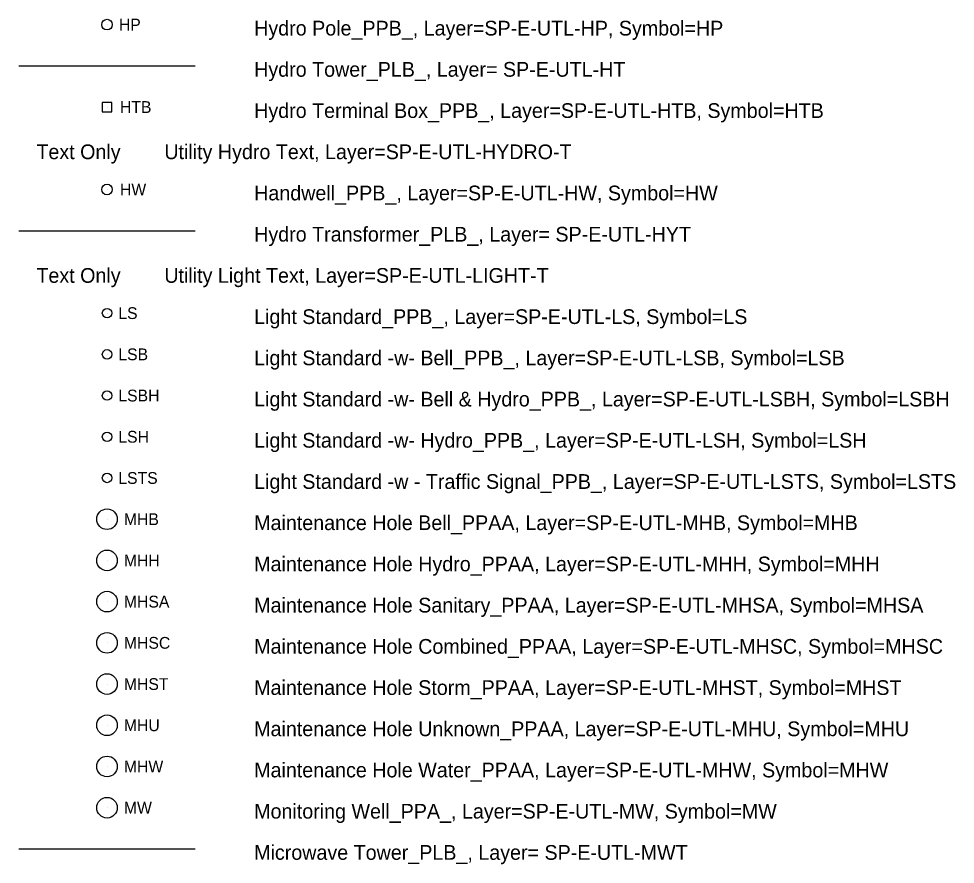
# Model space of a CAD drawing. Extents: x 500528 to 502626, y 4210261 to 4212624.
# Drawn here: x 500886.5 to 501045.7, y 4210853 to 4210996.6 of the extents above; entities that cross this region are included whole.
import ezdxf

# ---------------------------------------------------------------- set-up
doc = ezdxf.new("R2010")
doc.units = 0
for name, color, linetype in [('SP-E-UTL-BELL-T', 7, 'Continuous'), ('SP-E-UTL-COMB-T', 7, 'Continuous'), ('SP-E-UTL-HP', 7, 'Continuous'), ('SP-E-UTL-HT', 7, 'Continuous'), ('SP-E-UTL-HTB', 7, 'Continuous'), ('SP-E-UTL-HW', 7, 'Continuous'), ('SP-E-UTL-HYDRO-T', 7, 'Continuous'), ('SP-E-UTL-HYT', 7, 'Continuous'), ('SP-E-UTL-LIGHT-T', 7, 'Continuous'), ('SP-E-UTL-LS', 7, 'Continuous'), ('SP-E-UTL-LSB', 7, 'Continuous'), ('SP-E-UTL-LSBH', 7, 'Continuous'), ('SP-E-UTL-LSH', 7, 'Continuous'), ('SP-E-UTL-LSTS', 7, 'Continuous'), ('SP-E-UTL-MHB', 7, 'Continuous'), ('SP-E-UTL-MHH', 7, 'Continuous'), ('SP-E-UTL-MHSA', 7, 'Continuous'), ('SP-E-UTL-MHSC', 7, 'Continuous'), ('SP-E-UTL-MHST', 7, 'Continuous'), ('SP-E-UTL-MHU', 7, 'Continuous'), ('SP-E-UTL-MHW', 7, 'Continuous'), ('SP-E-UTL-MW', 7, 'Continuous'), ('SP-E-UTL-MWT', 7, 'Continuous'), ('SP-E-UTL-SAN-ST-COMB-T', 7, 'Continuous'), ('SP-E-UTL-SAN-T', 7, 'Continuous'), ('SP-E-UTL-STORM-T', 7, 'Continuous'), ('SP-E-UTL-T', 7, 'Continuous'), ('SP-E-UTL-WATER-T', 7, 'Continuous')]:
    doc.layers.add(name, color=color, linetype=linetype)

# ---------------------------------------------------------------- blocks, each defined once
blk = doc.blocks.new('HP')
at = {"layer": 'SP-E-UTL-HP'}
blk.add_lwpolyline([(0, 0), (0, 0)], dxfattribs=at)
blk.add_circle((0, 0), 0.09, dxfattribs=at)
at = {"layer": 'SP-E-UTL-HYDRO-T'}
blk.add_text('HP', height=0.2, dxfattribs=at).set_placement((0.202, -0.1))
blk = doc.blocks.new('HTB')
at = {"layer": 'SP-E-UTL-HTB'}
for points in [[(-0.08, 0.08), (-0.08, -0.08), (0.08, -0.08), (0.08, 0.08), (-0.08, 0.08)], [(0, 0), (0, 0)]]:
    blk.add_lwpolyline(points, dxfattribs=at)
at = {"layer": 'SP-E-UTL-HYDRO-T'}
blk.add_text('HTB', height=0.2, dxfattribs=at).set_placement((0.22, -0.1))
blk = doc.blocks.new('HW')
at = {"layer": 'SP-E-UTL-HW'}
blk.add_lwpolyline([(0, 0), (0, 0)], dxfattribs=at)
blk.add_circle((0, 0), 0.09, dxfattribs=at)
at = {"layer": 'SP-E-UTL-T'}
blk.add_text('HW', height=0.2, dxfattribs=at).set_placement((0.22, -0.1))
blk = doc.blocks.new('LS')
at = {"layer": 'SP-E-UTL-LS'}
blk.add_lwpolyline([(0, 0), (0, 0)], dxfattribs=at)
blk.add_circle((0, 0), 0.08, dxfattribs=at)
at = {"layer": 'SP-E-UTL-LIGHT-T'}
blk.add_text('LS', height=0.2, dxfattribs=at).set_placement((0.192, -0.1))
blk = doc.blocks.new('LSB')
at = {"layer": 'SP-E-UTL-LSB'}
blk.add_lwpolyline([(0, 0), (0, 0)], dxfattribs=at)
blk.add_circle((0, 0), 0.08, dxfattribs=at)
at = {"layer": 'SP-E-UTL-COMB-T'}
blk.add_text('LSB', height=0.2, dxfattribs=at).set_placement((0.192, -0.1))
blk = doc.blocks.new('LSBH')
at = {"layer": 'SP-E-UTL-LSBH'}
blk.add_lwpolyline([(0, 0), (0, 0)], dxfattribs=at)
blk.add_circle((0, 0), 0.08, dxfattribs=at)
at = {"layer": 'SP-E-UTL-COMB-T'}
blk.add_text('LSBH', height=0.2, dxfattribs=at).set_placement((0.192, -0.1))
blk = doc.blocks.new('LSH')
at = {"layer": 'SP-E-UTL-LSH'}
blk.add_lwpolyline([(0, 0), (0, 0)], dxfattribs=at)
blk.add_circle((0, 0), 0.08, dxfattribs=at)
at = {"layer": 'SP-E-UTL-COMB-T'}
blk.add_text('LSH', height=0.2, dxfattribs=at).set_placement((0.192, -0.1))
blk = doc.blocks.new('LSTS')
at = {"layer": 'SP-E-UTL-LSTS'}
blk.add_lwpolyline([(0, 0), (0, 0)], dxfattribs=at)
blk.add_circle((0, 0), 0.08, dxfattribs=at)
at = {"layer": 'SP-E-UTL-COMB-T'}
blk.add_text('LSTS', height=0.2, dxfattribs=at).set_placement((0.192, -0.1))
blk = doc.blocks.new('MHB')
at = {"layer": 'SP-E-UTL-MHB'}
blk.add_lwpolyline([(0, 0), (0, 0)], dxfattribs=at)
blk.add_circle((0, 0), 0.175, dxfattribs=at)
at = {"layer": 'SP-E-UTL-BELL-T'}
blk.add_text('MHB', height=0.2, dxfattribs=at).set_placement((0.287, -0.1))
blk = doc.blocks.new('MHH')
at = {"layer": 'SP-E-UTL-MHH'}
blk.add_lwpolyline([(0, 0), (0, 0)], dxfattribs=at)
blk.add_circle((0, 0), 0.175, dxfattribs=at)
at = {"layer": 'SP-E-UTL-HYDRO-T'}
blk.add_text('MHH', height=0.2, dxfattribs=at).set_placement((0.287, -0.1))
blk = doc.blocks.new('MHSA')
at = {"layer": 'SP-E-UTL-MHSA'}
blk.add_lwpolyline([(0, 0), (0, 0)], dxfattribs=at)
blk.add_circle((0, 0), 0.175, dxfattribs=at)
at = {"layer": 'SP-E-UTL-SAN-T'}
blk.add_text('MHSA', height=0.2, dxfattribs=at).set_placement((0.287, -0.1))
blk = doc.blocks.new('MHSC')
at = {"layer": 'SP-E-UTL-MHSC'}
blk.add_lwpolyline([(0, 0), (0, 0)], dxfattribs=at)
blk.add_circle((0, 0), 0.175, dxfattribs=at)
at = {"layer": 'SP-E-UTL-SAN-ST-COMB-T'}
blk.add_text('MHSC', height=0.2, dxfattribs=at).set_placement((0.287, -0.1))
blk = doc.blocks.new('MHST')
at = {"layer": 'SP-E-UTL-MHST'}
blk.add_lwpolyline([(0, 0), (0, 0)], dxfattribs=at)
blk.add_circle((0, 0), 0.175, dxfattribs=at)
at = {"layer": 'SP-E-UTL-STORM-T'}
blk.add_text('MHST', height=0.2, dxfattribs=at).set_placement((0.287, -0.1))
blk = doc.blocks.new('MHU')
at = {"layer": 'SP-E-UTL-MHU'}
blk.add_lwpolyline([(0, 0), (0, 0)], dxfattribs=at)
blk.add_circle((0, 0), 0.175, dxfattribs=at)
at = {"layer": 'SP-E-UTL-T'}
blk.add_text('MHU', height=0.2, dxfattribs=at).set_placement((0.287, -0.1))
blk = doc.blocks.new('MHW')
at = {"layer": 'SP-E-UTL-MHW'}
blk.add_lwpolyline([(0, 0), (0, 0)], dxfattribs=at)
blk.add_circle((0, 0), 0.175, dxfattribs=at)
at = {"layer": 'SP-E-UTL-WATER-T'}
blk.add_text('MHW', height=0.2, dxfattribs=at).set_placement((0.287, -0.1))
blk = doc.blocks.new('MW')
at = {"layer": 'SP-E-UTL-MW'}
blk.add_lwpolyline([(0, 0), (0, 0)], dxfattribs=at)
blk.add_circle((0, 0), 0.175, dxfattribs=at)
at = {"layer": 'SP-E-UTL-T'}
blk.add_text('MW', height=0.2, dxfattribs=at).set_placement((0.287, -0.1))

msp = doc.modelspace()

# ---------------------------------------------------------------- linework, layer by layer
at = {"layer": 'SP-E-UTL-HT'}
msp.add_line((500886.55, 4210988.59), (500916.55, 4210988.59), dxfattribs=at)
at = {"layer": 'SP-E-UTL-HYT'}
msp.add_line((500886.55, 4210960.59), (500916.55, 4210960.59), dxfattribs=at)
at = {"layer": 'SP-E-UTL-MWT'}
msp.add_line((500886.55, 4210855.59), (500916.55, 4210855.59), dxfattribs=at)

# ---------------------------------------------------------------- block references
at = {"layer": 'SP-E-UTL-HP', "xscale": 10, "yscale": 10}
msp.add_blockref('HP', (500901.55, 4210995.59), dxfattribs=at)
at = {"layer": 'SP-E-UTL-HTB', "xscale": 10, "yscale": 10}
msp.add_blockref('HTB', (500901.55, 4210981.59), dxfattribs=at)
at = {"layer": 'SP-E-UTL-HW', "xscale": 10, "yscale": 10}
msp.add_blockref('HW', (500901.55, 4210967.59), dxfattribs=at)
at = {"layer": 'SP-E-UTL-LS', "xscale": 10, "yscale": 10}
msp.add_blockref('LS', (500901.55, 4210946.59), dxfattribs=at)
at = {"layer": 'SP-E-UTL-LSB', "xscale": 10, "yscale": 10}
msp.add_blockref('LSB', (500901.55, 4210939.59), dxfattribs=at)
at = {"layer": 'SP-E-UTL-LSBH', "xscale": 10, "yscale": 10}
msp.add_blockref('LSBH', (500901.55, 4210932.59), dxfattribs=at)
at = {"layer": 'SP-E-UTL-LSH', "xscale": 10, "yscale": 10}
msp.add_blockref('LSH', (500901.55, 4210925.59), dxfattribs=at)
at = {"layer": 'SP-E-UTL-LSTS', "xscale": 10, "yscale": 10}
msp.add_blockref('LSTS', (500901.55, 4210918.59), dxfattribs=at)
at = {"layer": 'SP-E-UTL-MHB', "xscale": 10, "yscale": 10}
msp.add_blockref('MHB', (500901.55, 4210911.59), dxfattribs=at)
at = {"layer": 'SP-E-UTL-MHH', "xscale": 10, "yscale": 10}
msp.add_blockref('MHH', (500901.55, 4210904.59), dxfattribs=at)
at = {"layer": 'SP-E-UTL-MHSA', "xscale": 10, "yscale": 10}
msp.add_blockref('MHSA', (500901.55, 4210897.59), dxfattribs=at)
at = {"layer": 'SP-E-UTL-MHSC', "xscale": 10, "yscale": 10}
msp.add_blockref('MHSC', (500901.55, 4210890.59), dxfattribs=at)
at = {"layer": 'SP-E-UTL-MHST', "xscale": 10, "yscale": 10}
msp.add_blockref('MHST', (500901.55, 4210883.59), dxfattribs=at)
at = {"layer": 'SP-E-UTL-MHU', "xscale": 10, "yscale": 10}
msp.add_blockref('MHU', (500901.55, 4210876.59), dxfattribs=at)
at = {"layer": 'SP-E-UTL-MHW', "xscale": 10, "yscale": 10}
msp.add_blockref('MHW', (500901.55, 4210869.59), dxfattribs=at)
at = {"layer": 'SP-E-UTL-MW', "xscale": 10, "yscale": 10}
msp.add_blockref('MW', (500901.55, 4210862.59), dxfattribs=at)

# ---------------------------------------------------------------- texts
at = {"layer": 'SP-E-UTL-HP'}
msp.add_text('Hydro Pole_PPB_, Layer=SP-E-UTL-HP, Symbol=HP ', height=2.5, dxfattribs=at).set_placement((500926.55, 4210993.74))
at = {"layer": 'SP-E-UTL-HT'}
msp.add_text('Hydro Tower_PLB_, Layer= SP-E-UTL-HT ', height=2.5, dxfattribs=at).set_placement((500926.55, 4210986.74))
at = {"layer": 'SP-E-UTL-HTB'}
msp.add_text('Hydro Terminal Box_PPB_, Layer=SP-E-UTL-HTB, Symbol=HTB ', height=2.5, dxfattribs=at).set_placement((500926.55, 4210979.74))
at = {"layer": 'SP-E-UTL-HW'}
msp.add_text('Handwell_PPB_, Layer=SP-E-UTL-HW, Symbol=HW ', height=2.5, dxfattribs=at).set_placement((500926.55, 4210965.74))
at = {"layer": 'SP-E-UTL-HYDRO-T'}
msp.add_text('Text Only        Utility Hydro Text, Layer=SP-E-UTL-HYDRO-T', height=2.5, dxfattribs=at).set_placement((500889.55, 4210972.74))
at = {"layer": 'SP-E-UTL-HYT'}
msp.add_text('Hydro Transformer_PLB_, Layer= SP-E-UTL-HYT ', height=2.5, dxfattribs=at).set_placement((500926.55, 4210958.74))
at = {"layer": 'SP-E-UTL-LIGHT-T'}
msp.add_text('Text Only        Utility Light Text, Layer=SP-E-UTL-LIGHT-T', height=2.5, dxfattribs=at).set_placement((500889.55, 4210951.74))
at = {"layer": 'SP-E-UTL-LS'}
msp.add_text('Light Standard_PPB_, Layer=SP-E-UTL-LS, Symbol=LS ', height=2.5, dxfattribs=at).set_placement((500926.55, 4210944.74))
at = {"layer": 'SP-E-UTL-LSB'}
msp.add_text('Light Standard -w- Bell_PPB_, Layer=SP-E-UTL-LSB, Symbol=LSB ', height=2.5, dxfattribs=at).set_placement((500926.55, 4210937.74))
at = {"layer": 'SP-E-UTL-LSBH'}
msp.add_text('Light Standard -w- Bell & Hydro_PPB_, Layer=SP-E-UTL-LSBH, Symbol=LSBH ', height=2.5, dxfattribs=at).set_placement((500926.55, 4210930.74))
at = {"layer": 'SP-E-UTL-LSH'}
msp.add_text('Light Standard -w- Hydro_PPB_, Layer=SP-E-UTL-LSH, Symbol=LSH ', height=2.5, dxfattribs=at).set_placement((500926.55, 4210923.74))
at = {"layer": 'SP-E-UTL-LSTS'}
msp.add_text('Light Standard -w - Traffic Signal_PPB_, Layer=SP-E-UTL-LSTS, Symbol=LSTS ', height=2.5, dxfattribs=at).set_placement((500926.55, 4210916.74))
at = {"layer": 'SP-E-UTL-MHB'}
msp.add_text('Maintenance Hole Bell_PPAA, Layer=SP-E-UTL-MHB, Symbol=MHB ', height=2.5, dxfattribs=at).set_placement((500926.55, 4210909.74))
at = {"layer": 'SP-E-UTL-MHH'}
msp.add_text('Maintenance Hole Hydro_PPAA, Layer=SP-E-UTL-MHH, Symbol=MHH ', height=2.5, dxfattribs=at).set_placement((500926.55, 4210902.74))
at = {"layer": 'SP-E-UTL-MHSA'}
msp.add_text('Maintenance Hole Sanitary_PPAA, Layer=SP-E-UTL-MHSA, Symbol=MHSA ', height=2.5, dxfattribs=at).set_placement((500926.55, 4210895.74))
at = {"layer": 'SP-E-UTL-MHSC'}
msp.add_text('Maintenance Hole Combined_PPAA, Layer=SP-E-UTL-MHSC, Symbol=MHSC ', height=2.5, dxfattribs=at).set_placement((500926.55, 4210888.74))
at = {"layer": 'SP-E-UTL-MHST'}
msp.add_text('Maintenance Hole Storm_PPAA, Layer=SP-E-UTL-MHST, Symbol=MHST ', height=2.5, dxfattribs=at).set_placement((500926.55, 4210881.74))
at = {"layer": 'SP-E-UTL-MHU'}
msp.add_text('Maintenance Hole Unknown_PPAA, Layer=SP-E-UTL-MHU, Symbol=MHU ', height=2.5, dxfattribs=at).set_placement((500926.55, 4210874.74))
at = {"layer": 'SP-E-UTL-MHW'}
msp.add_text('Maintenance Hole Water_PPAA, Layer=SP-E-UTL-MHW, Symbol=MHW ', height=2.5, dxfattribs=at).set_placement((500926.55, 4210867.74))
at = {"layer": 'SP-E-UTL-MW'}
msp.add_text('Monitoring Well_PPA_, Layer=SP-E-UTL-MW, Symbol=MW ', height=2.5, dxfattribs=at).set_placement((500926.55, 4210860.74))
at = {"layer": 'SP-E-UTL-MWT'}
msp.add_text('Microwave Tower_PLB_, Layer= SP-E-UTL-MWT ', height=2.5, dxfattribs=at).set_placement((500926.55, 4210853.74))

doc.saveas('drawing.dxf')
